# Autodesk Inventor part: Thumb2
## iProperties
Company: cbliss@cbliss.com
Author: Charles Bliss
Shininess: 0.0
PropertySet Name: _Private Model Information
Created: 2000-01
Part Number: Thumb2
Project: Inventor Sample
Document SubType Name: Modeling
Designer: Charles Bliss
Control State: 0
Master: False
Checked Out: False
Density: 0.0
Volume: 0.0
Area: 0.0
PropertySet Name: Model Information
